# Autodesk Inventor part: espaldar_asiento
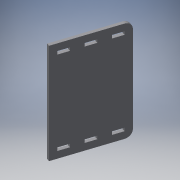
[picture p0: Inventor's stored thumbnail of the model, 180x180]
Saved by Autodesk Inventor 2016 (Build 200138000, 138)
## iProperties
Created: 2017-06
Part Number: espaldar_asiento
Material: Generic
Document SubType Name: Modeling
Designer: laboratorioesan
Density: 1 g/cm^3
Appearance: Default
Author: laboratorioesan
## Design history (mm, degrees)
sketch "Sketch1"
  geometry: L1 (0, 0)-(490, 0) reference; L2 (490, 0)-(490, 18.5) reference; L3 (0, 18.5)-(490, 18.5) reference; L4 (0, 0)-(0, 18.5) reference; L5 (854, -205.5)-(854, -75.5) reference; L6 (872.5, -75.5)-(872.5, -205.5) reference; L7 (872.5, -75.5)-(854, -75.5) reference; L8 (854, -205.5)-(854, -75.5) reference; L9 (872.5, -205.5)-(854, -205.5) reference; L10 (490, 18.5)-(613.607, 398.923); L11 (613.607, 398.923)-(631.201, 393.206); L12 (631.201, 393.206)-(507.595, 12.783); L13 (490, 18.5)-(507.595, 12.783)
  constraints: 8 end point, 3 perpendicular
  dimensions: "d0" = 18.5 distance of L10.end L11.end; "d1" = 18 deg angle of L2 L10; "d2" = 400 distance of L2.end L10.end
extrude "Extrusion1" new body sketch "Sketch1" distance "d3" = 600; taper "d4" = 0 deg
fillet "Fillet1" dims "d5" = 40
sketch "Sketch2"
  geometry: L1 (40, 400)-(560, 400) reference; L2 (0, 0)-(0, 360) reference; L3 (0, 0)-(600, 0) reference; L4 (600, 360)-(600, 0) reference; L5 (40, 360)-(58.5, 360); L6 (58.5, 360)-(58.5, 300); L7 (58.5, 300)-(40, 300); L8 (40, 300)-(40, 360); L9 (40, 230)-(58.5, 230); L10 (58.5, 230)-(58.5, 170); L11 (58.5, 170)-(40, 170); L12 (40, 170)-(40, 230); L13 (40, 100)-(58.5, 100); L14 (58.5, 100)-(58.5, 40); L15 (58.5, 40)-(40, 40); L16 (40, 40)-(40, 100); L17 (300, 400)-(300, 360); L18 (541.5, 170)-(560, 170); L19 (541.5, 230)-(541.5, 170); L20 (560, 170)-(560, 230); L21 (560, 230)-(541.5, 230); L22 (541.5, 300)-(560, 300); L23 (541.5, 360)-(541.5, 300); L24 (560, 300)-(560, 360); L25 (560, 360)-(541.5, 360); L26 (541.5, 100)-(541.5, 40); L27 (541.5, 40)-(560, 40); L28 (560, 40)-(560, 100); L29 (560, 100)-(541.5, 100); A1 r 40 centre (560, 360) between (600, 360) and (560, 400) reference; A2 r 40 centre (40, 360) between (40, 400) and (0, 360) reference; 2 further points
  constraints: 50 end point, 13 symmetric about line, 6 parallel, 4 point on line, 3 horizontal, 3 perpendicular, 1 midpoint, 1 vertical
  dimensions: "d6" = 18.5 distance of L6.end L7.end; "d7" = 60 distance of L5.end L6.end; "d8" = 40 distance between parallel lines of L1 L5; "d9" = 60 distance of L9.end L10.end; "d10" = 60 distance of L13.end L14.end; "d11" = 70 distance between parallel lines of L7 L9; "d12" = 70 distance between parallel lines of L13 L11
extrude "Extrusion2" cut sketch "Sketch2" distance "d13" = 18.5; taper "d14" = 0 deg
body "Solid1"
node "Reference1"
node "Reference2"
node "Reference3"
node "Projected Loop1"
